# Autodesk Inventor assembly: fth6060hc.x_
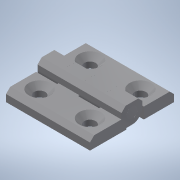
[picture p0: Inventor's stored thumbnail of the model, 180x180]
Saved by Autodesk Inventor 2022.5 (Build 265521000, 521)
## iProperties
Part Number: fth6060hc.x_
Material: 一般
Document SubType Name: Assembly
Designer: ImaoCorp
Sending System: SOLIDWORKS 2017-2017317
MC: AMD64
MC_MODEL: Intel64 Family 6 Model 60 Stepping 3, GenuineIntel
OS: Windows_NT
FRU: Parasolid Version 29.0, build 201,  4-17-2017
FORMAT: text
GUISE: transmit
KEY: fth6060hc
FILE: fth6060hc.x_t
DATE: Mon May 13 14:28:35 2019
Author: ImaoCorp
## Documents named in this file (4)
- X:\14_SW2022-Inv2022\00_全2023-1023新製品(TCC)まで\f\fth6060hc\FTH6060HC.iam
- X:\14_SW2022-Inv2022\00_全2023-1023新製品(TCC)まで\f\fth6060hc\fth6060hc_01.ipt
- X:\14_SW2022-Inv2022\00_全2023-1023新製品(TCC)まで\f\fth6060hc\fth6060hc_02.ipt
- X:\14_SW2022-Inv2022\00_全2023-1023新製品(TCC)まで\f\fth6060hc\fth6060hc_03.ipt
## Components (3 placed, 3 different names)
1. fth6060hc_01
2. fth6060hc_02
3. fth6060hc_03
